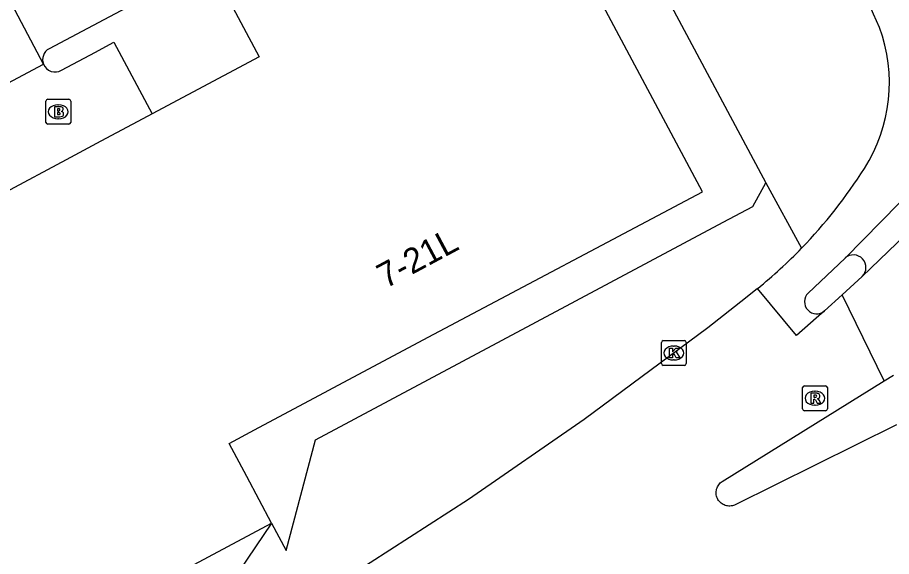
# Model space of a CAD drawing. Extents: x 160304 to 160954, y 383686 to 384161.
# Drawn here: x 160822.82 to 160858.01, y 383917.88 to 383939.55 of the extents above; entities that cross this region are included whole.
import ezdxf

# ---------------------------------------------------------------- set-up
doc = ezdxf.new("R2010")
doc.units = 0
for name, color, linetype in [('IMGEO_Brandkraan', 7, 'Continuous'), ('IMGEO_Fietspad_open', 7, 'Continuous'), ('IMGEO_Kolk', 7, 'Continuous'), ('IMGEO_Pand', 7, 'Continuous'), ('IMGEO_Pand_nummerreeks', 7, 'Continuous'), ('IMGEO_Parkeervlak_open', 7, 'Continuous'), ('IMGEO_Rijbaan_lokaal_open', 7, 'Continuous'), ('IMGEO_Rioolput', 7, 'Continuous'), ('IMGEO_Voetpad_open', 7, 'Continuous')]:
    doc.layers.add(name, color=color, linetype=linetype)

msp = doc.modelspace()

# ---------------------------------------------------------------- linework, layer by layer
at = {"layer": 'IMGEO_Brandkraan'}
for p, q in [((160824.037, 383936.264), (160824.889, 383936.264)), ((160823.962, 383935.338), (160823.962, 383936.19)), ((160824.45, 383936.044), (160824.475, 383936.044)), ((160824.963, 383936.19), (160824.963, 383935.338)), ((160824.889, 383935.264), (160824.037, 383935.264)), ((160824.473, 383935.484), (160824.448, 383935.484))]:
    msp.add_line(p, q, dxfattribs=at)
for points in [[(160824.037, 383936.264), (160824.889, 383936.264)], [(160823.962, 383935.338), (160823.962, 383936.19)], [(160824.31, 383935.964), (160824.31, 383935.564), (160824.523, 383935.564)], [(160824.541, 383935.964), (160824.31, 383935.964)], [(160824.489, 383935.883), (160824.435, 383935.883), (160824.435, 383935.807)], [(160824.963, 383936.19), (160824.963, 383935.338)], [(160824.435, 383935.807), (160824.488, 383935.807)], [(160824.497, 383935.731), (160824.435, 383935.731), (160824.435, 383935.65)], [(160824.435, 383935.65), (160824.497, 383935.65)], [(160824.889, 383935.264), (160824.037, 383935.264)]]:
    msp.add_lwpolyline(points, dxfattribs=at)
for centre, radius, start, end in [((160824.039, 383936.188), 0.0765, 91.552, 178.448), ((160824.039, 383936.188), 0.0765, 91.552, 178.448), ((160824.887, 383936.188), 0.0765, 1.552, 88.448), ((160824.887, 383936.188), 0.0765, 1.552, 88.448), ((160824.49, 383935.845), 0.0379, 267.8285, 90.9355), ((160824.545, 383935.819), 0.145, 59.4692, 91.5367), ((160824.57, 383935.866), 0.0922, 285.5137, 58.1501), ((160824.498, 383935.69), 0.0404, 269.8759, 90.5077), ((160824.529, 383935.815), 0.251, 268.6676, 293.5347), ((160824.575, 383935.674), 0.105, 301.3115, 78.989), ((160824.039, 383935.34), 0.0765, 181.552, 268.448), ((160824.039, 383935.34), 0.0765, 181.552, 268.448), ((160824.887, 383935.34), 0.0765, 271.552, 358.448), ((160824.887, 383935.34), 0.0765, 271.552, 358.448)]:
    msp.add_arc(centre, radius, start, end, dxfattribs=at)
for centre, major_axis, ratio, start_param, end_param in [((160824.449, 383935.764), (-0.387, 0.002), 0.722429, 4.712389, 7.853982), ((160824.474, 383935.764), (-0.39, 0.002), 0.717154, 1.570796, 4.712389)]:
    msp.add_ellipse(centre, major_axis=major_axis, ratio=ratio, start_param=start_param, end_param=end_param, dxfattribs=at)
at = {"layer": 'IMGEO_Fietspad_open'}
for points in [[(160856.142, 383929.882), (160859.047, 383932.822)], [(160854.653, 383928.473), (160856.142, 383929.882)]]:
    msp.add_lwpolyline(points, dxfattribs=at)
for centre, radius, start, end in [((160519.197, 383790.477), 369.555, 23.72347, 24.43672), ((160851.538, 383936.927), 6.388, 327.4065, 20.4345), ((160839.739, 383944.438), 20.375, 315.99, 327.4842), ((160839.551, 383944.651), 20.658, 309.2531, 315.9288), ((160854.999, 383928.125), 0.491, 134.8796, 310.3279)]:
    msp.add_arc(centre, radius, start, end, dxfattribs=at)
at = {"layer": 'IMGEO_Kolk'}
for p, q in [((160848.748, 383925.635), (160848.748, 383926.487)), ((160848.823, 383926.561), (160849.675, 383926.561)), ((160849.749, 383926.487), (160849.749, 383925.635)), ((160849.236, 383926.341), (160849.261, 383926.341)), ((160849.259, 383925.781), (160849.234, 383925.781)), ((160849.675, 383925.561), (160848.823, 383925.561))]:
    msp.add_line(p, q, dxfattribs=at)
for points in [[(160848.748, 383925.635), (160848.748, 383926.487)], [(160848.823, 383926.561), (160849.675, 383926.561)], [(160849.749, 383926.487), (160849.749, 383925.635)], [(160849.069, 383926.261), (160849.192, 383926.261), (160849.192, 383926.11), (160849.322, 383926.261), (160849.486, 383926.261), (160849.34, 383926.11), (160849.493, 383925.861), (160849.341, 383925.861), (160849.256, 383926.025), (160849.192, 383925.958), (160849.192, 383925.861), (160849.069, 383925.861), (160849.069, 383926.261)], [(160849.675, 383925.561), (160848.823, 383925.561)]]:
    msp.add_lwpolyline(points, dxfattribs=at)
for centre, start, end in [((160848.825, 383926.485), 91.552, 178.448), ((160848.825, 383926.485), 91.552, 178.448), ((160849.673, 383926.485), 1.552, 88.448), ((160849.673, 383926.485), 1.552, 88.448), ((160848.825, 383925.637), 181.552, 268.448), ((160848.825, 383925.637), 181.552, 268.448), ((160849.673, 383925.637), 271.552, 358.448), ((160849.673, 383925.637), 271.552, 358.448)]:
    msp.add_arc(centre, 0.0765, start, end, dxfattribs=at)
for centre, major_axis, ratio, start_param, end_param in [((160849.235, 383926.061), (-0.387, 0.002), 0.722429, 4.712389, 7.853982), ((160849.26, 383926.061), (-0.39, 0.002), 0.717154, 1.570796, 4.712389)]:
    msp.add_ellipse(centre, major_axis=major_axis, ratio=ratio, start_param=start_param, end_param=end_param, dxfattribs=at)
at = {"layer": 'IMGEO_Pand'}
for points in [[(160833.051, 383919.216), (160832.05, 383921.094), (160831.34, 383922.427), (160832.368, 383922.975), (160835.356, 383924.567), (160839.36, 383926.701), (160850.402, 383932.537), (160836.537, 383958.48)], [(160827.604, 383953.706), (160824.925, 383952.248), (160824.98, 383952.146), (160826.002, 383950.231), (160826.429, 383949.432), (160832.548, 383937.978), (160828.242, 383935.678)], [(160828.242, 383935.678), (160828.067, 383935.585), (160826.179, 383934.576), (160824.786, 383933.833), (160819.857, 383931.2)], [(160805.533, 383904.534), (160833.051, 383919.216)]]:
    msp.add_lwpolyline(points, dxfattribs=at)
at = {"layer": 'IMGEO_Parkeervlak_open'}
msp.add_lwpolyline([(160823.414, 383949.093), (160823.931, 383948.129), (160828.069, 383940.418), (160824.093, 383938.301)], dxfattribs=at)
msp.add_arc((160824.329, 383937.866), 0.495, 118.5285, 202.1872, dxfattribs=at)
at = {"layer": 'IMGEO_Rijbaan_lokaal_open'}
for points in [[(160823.871, 383937.679), (160818.53, 383947.772)], [(160818.159, 383934.648), (160823.871, 383937.679)], [(160859.971, 383932.161), (160856.834, 383929.139)], [(160856.834, 383929.139), (160856.029, 383928.402)], [(160852.622, 383928.654), (160852.134, 383928.269), (160850.618, 383927.076), (160845.642, 383923.381), (160840.984, 383920.171), (160829.889, 383913.034), (160815.719, 383903.242), (160806.965, 383896.183), (160806.937, 383896.163), (160806.492, 383895.876), (160806.023, 383895.631), (160805.534, 383895.428), (160805.029, 383895.27), (160804.512, 383895.158), (160803.987, 383895.092), (160803.458, 383895.073), (160803.345, 383895.079)], [(160855.317, 383927.751), (160854.187, 383926.77), (160852.622, 383928.654)], [(160856.029, 383928.402), (160855.317, 383927.751)], [(160857.722, 383924.941), (160856.029, 383928.402)], [(160857.722, 383924.941), (160858.097, 383925.173)], [(160858.211, 383923.166), (160851.722, 383919.958), (160851.695, 383919.946), (160851.65, 383919.93), (160851.603, 383919.917), (160851.555, 383919.909), (160851.507, 383919.906), (160851.459, 383919.906), (160851.411, 383919.911), (160851.364, 383919.92), (160851.317, 383919.933), (160851.272, 383919.951), (160851.229, 383919.972), (160851.188, 383919.997), (160851.149, 383920.026), (160851.113, 383920.058), (160851.08, 383920.093), (160851.05, 383920.131), (160851.024, 383920.172), (160851.001, 383920.214), (160850.983, 383920.259), (160850.968, 383920.305), (160850.958, 383920.352), (160850.951, 383920.4), (160850.95, 383920.448), (160850.952, 383920.496), (160850.959, 383920.544), (160850.97, 383920.591), (160850.985, 383920.637), (160851.004, 383920.681), (160851.027, 383920.724), (160851.054, 383920.764), (160851.084, 383920.801), (160851.117, 383920.836), (160851.154, 383920.868), (160851.193, 383920.896), (160857.722, 383924.941)]]:
    msp.add_lwpolyline(points, dxfattribs=at)
at = {"layer": 'IMGEO_Rioolput'}
for p, q in [((160854.429, 383923.816), (160854.429, 383924.668)), ((160854.504, 383924.742), (160855.356, 383924.742)), ((160855.43, 383924.668), (160855.43, 383923.816)), ((160854.917, 383924.522), (160854.942, 383924.522)), ((160854.94, 383923.962), (160854.915, 383923.962)), ((160855.356, 383923.742), (160854.504, 383923.742))]:
    msp.add_line(p, q, dxfattribs=at)
for points in [[(160854.429, 383923.816), (160854.429, 383924.668)], [(160854.504, 383924.742), (160855.356, 383924.742)], [(160855.43, 383924.668), (160855.43, 383923.816)], [(160855.018, 383924.44), (160854.766, 383924.442), (160854.766, 383924.042)], [(160854.944, 383924.361), (160854.89, 383924.361), (160854.89, 383924.28)], [(160854.89, 383924.28), (160854.942, 383924.28)], [(160854.766, 383924.042), (160854.89, 383924.042), (160854.89, 383924.204), (160854.901, 383924.204)], [(160854.948, 383924.175), (160855.019, 383924.042), (160855.159, 383924.042), (160855.094, 383924.168)], [(160855.356, 383923.742), (160854.504, 383923.742)]]:
    msp.add_lwpolyline(points, dxfattribs=at)
for centre, radius, start, end in [((160854.506, 383924.666), 0.0765, 91.552, 178.448), ((160854.506, 383924.666), 0.0765, 91.552, 178.448), ((160855.354, 383924.666), 0.0765, 1.552, 88.448), ((160855.354, 383924.666), 0.0765, 1.552, 88.448), ((160854.926, 383924.469), 0.19, 274.7715, 282.9687), ((160854.95, 383924.265), 0.0964, 77.0061, 93.1865), ((160854.964, 383924.322), 0.0378, 276.6634, 79.6772), ((160855.017, 383924.33), 0.109, 350.3612, 89.416), ((160855.015, 383924.33), 0.112, 277.5842, 350.9817), ((160854.9, 383924.151), 0.0533, 26.0293, 88.6989), ((160854.999, 383924.115), 0.108, 29.5134, 73.7905), ((160854.506, 383923.818), 0.0765, 181.552, 268.448), ((160854.506, 383923.818), 0.0765, 181.552, 268.448), ((160855.354, 383923.818), 0.0765, 271.552, 358.448), ((160855.354, 383923.818), 0.0765, 271.552, 358.448)]:
    msp.add_arc(centre, radius, start, end, dxfattribs=at)
for centre, major_axis, ratio, start_param, end_param in [((160854.916, 383924.242), (-0.387, 0.002), 0.722429, 4.712389, 7.853982), ((160854.941, 383924.242), (-0.39, 0.002), 0.717154, 1.570796, 4.712389)]:
    msp.add_ellipse(centre, major_axis=major_axis, ratio=ratio, start_param=start_param, end_param=end_param, dxfattribs=at)
at = {"layer": 'IMGEO_Voetpad_open'}
for points in [[(160838.66, 383959.615), (160852.951, 383932.906)], [(160824.59, 383937.43), (160825.967, 383938.166), (160826.528, 383938.466), (160826.698, 383938.557), (160828.242, 383935.678)], [(160833.051, 383919.216), (160833.635, 383918.122), (160834.823, 383922.573), (160851.23, 383931.319), (160852.428, 383931.958), (160852.951, 383932.906)], [(160852.951, 383932.906), (160854.393, 383930.282)], [(160833.051, 383919.216), (160831.42, 383916.815), (160831.505, 383916.657), (160807.312, 383903.772), (160807.237, 383903.913), (160805.698, 383904.226), (160805.533, 383904.534)]]:
    msp.add_lwpolyline(points, dxfattribs=at)
for centre, radius, start, end in [((160824.336, 383937.86), 0.499, 201.2096, 300.587), ((160856.473, 383929.497), 0.508, 315.2447, 130.6844)]:
    msp.add_arc(centre, radius, start, end, dxfattribs=at)

# ---------------------------------------------------------------- texts
at = {"layer": 'IMGEO_Pand_nummerreeks'}
msp.add_text('7-21L', height=1, rotation=28.1551, dxfattribs=at).set_placement((160837.645, 383928.638))

doc.saveas('drawing.dxf')
